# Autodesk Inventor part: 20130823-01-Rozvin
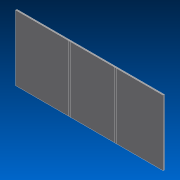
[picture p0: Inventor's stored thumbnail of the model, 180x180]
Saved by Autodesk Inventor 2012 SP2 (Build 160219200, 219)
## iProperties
Created: 2013-08
Part Number: 20130823-01-Rozvin
Material: Default
Document SubType Name: Plech
Designer: navara
Mass: 0.704254 g
Surface Area: 28.9836 cm^2
Volume: 0.704254 cm^3
Density: 1 g/cm^3
Sheet Metal Rule: Výchozí_mm
Author: navara
LastSaveDate: 12.04.2011
SM_Extents: 0x0
SM_Thickness: 0,5
SM_Length: 0
SM_Width: 0
SM_Style: Default_mm
VAHA: 0 kg
ROZMER_4: 0x0
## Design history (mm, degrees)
derived "20130823-01-Plech.ipt"
node "Rozvin1"
feature "Těleso1::20130823-01-Plech.ipt" dims "d0" = 10
tag "Prvek štítků1"
node "Těleso1"
other parameters: "Tloušťka" = 0.5 (derived), "KSoučinitel" = 4.4, "PoloměrOhybu" = 0.5 (= Tloušťka), "ŠířkaVýštipu" = 0.5 (= Tloušťka), "HloubkaVýštipu" = 0.25 (= 0.5 x Tloušťka), "VelikostRohovéhoVýštipu" = 2 (= 4 x Tloušťka), "MezeraVystřižení" = 0.01, "MinimálníZbytek" = 1 (= 2 x Tloušťka), "PřechodovýPoloměr" = 0.5 (= PoloměrOhybu), "VelikostJacobihoPoloměru" = 0.5 (= PoloměrOhybu), "VelikostMezery" = 0.5 (= Tloušťka)
